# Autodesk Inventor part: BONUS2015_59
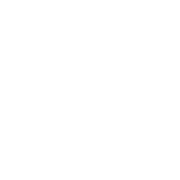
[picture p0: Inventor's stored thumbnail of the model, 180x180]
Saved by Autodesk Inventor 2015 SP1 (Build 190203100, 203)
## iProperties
Created: 2015-05
Part Number: BONUS2015_59
Material: Generisch
Document SubType Name: Modeling
Density: 1 g/cm^3
Appearance: Vorgabe
xx: 59
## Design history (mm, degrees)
